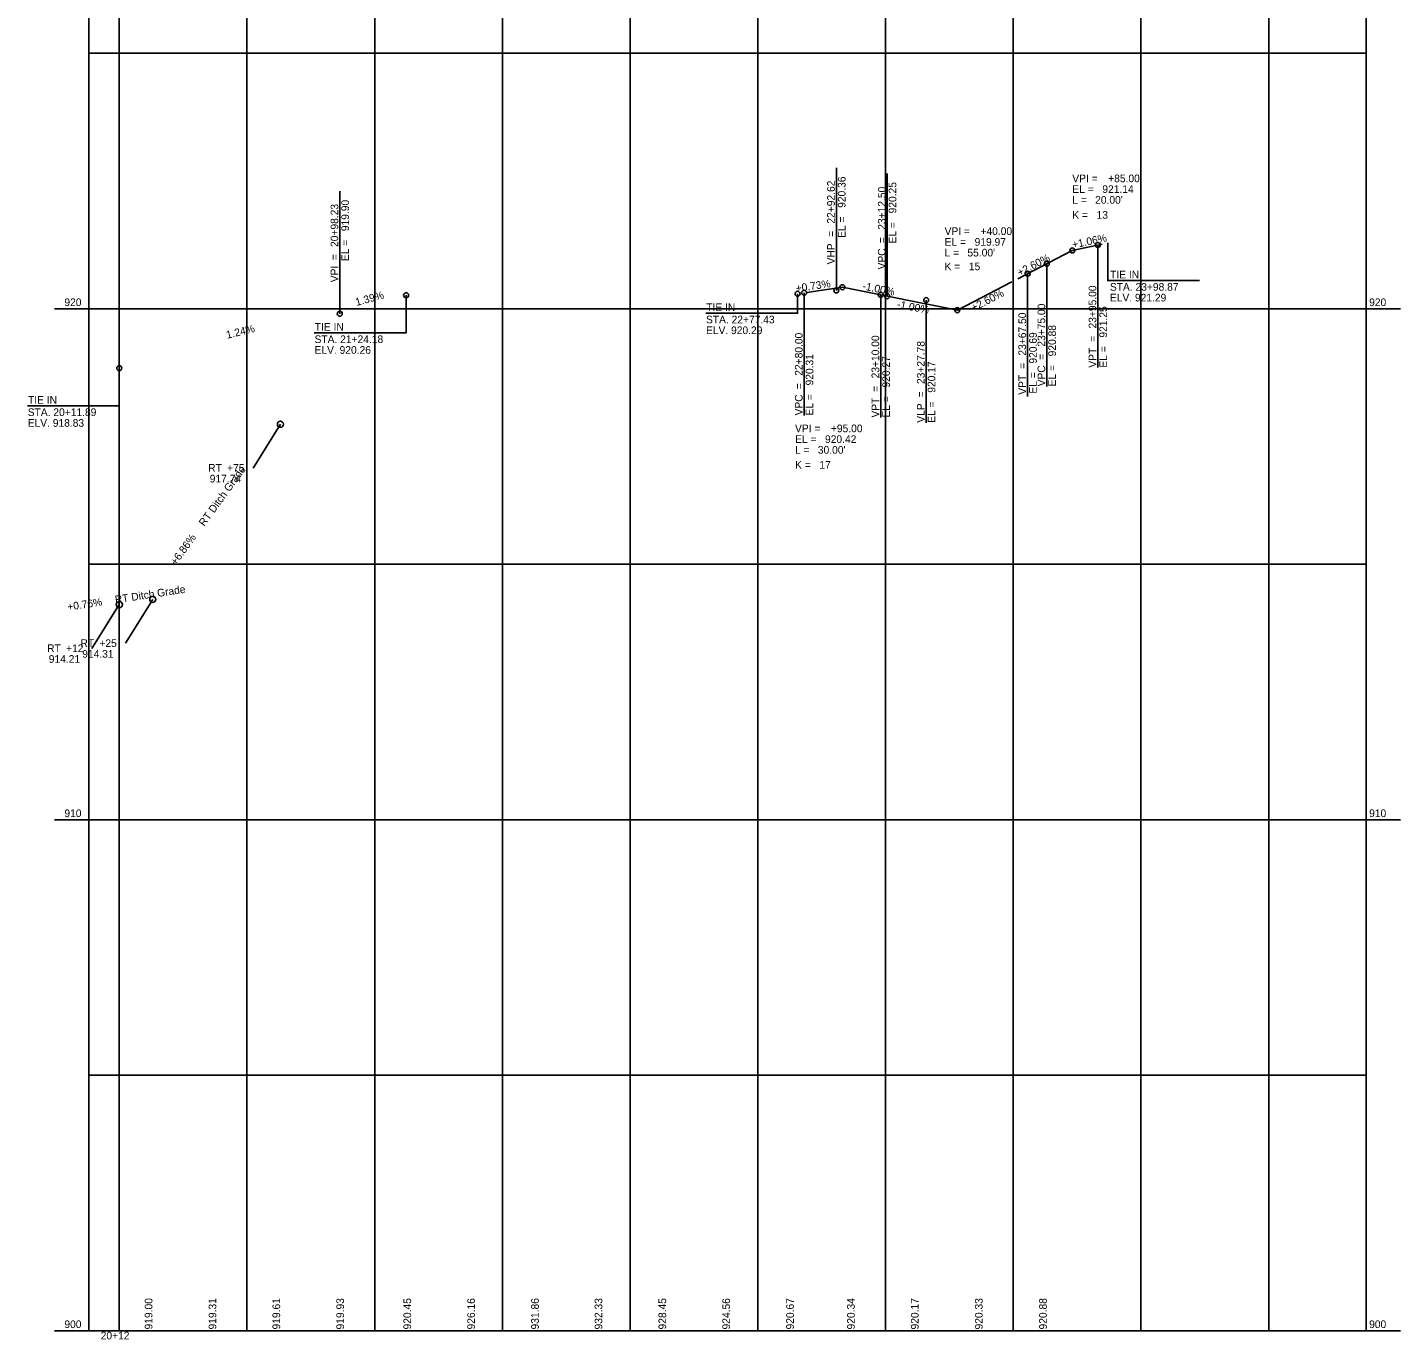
# Model space of a CAD drawing. Extents: x -36 to 502, y 897 to 1904.
# Drawn here: x -36 to 502, y 897 to 1410 of the extents above; entities that cross this region are included whole.
import ezdxf

# ---------------------------------------------------------------- set-up
doc = ezdxf.new("R2010")
doc.units = 0
for name, color, linetype in [('Text', 7, 'Continuous'), ('TextAlignment', 7, 'Continuous'), ('TextNonPlot', 7, 'Continuous')]:
    doc.layers.add(name, color=color, linetype=linetype)

msp = doc.modelspace()

# ---------------------------------------------------------------- linework, layer by layer
at = {"layer": 'Text'}
for centre in [(373.11, 1322.8), (383.11, 1324.93), (363.11, 1317.6), (355.61, 1313.7), (265.54, 1305.85), (268.11, 1306.22), (283.11, 1308.4), (298.11, 1305.4), (112.29, 1305.26), (300.61, 1304.9), (86.34, 1298.03), (328.11, 1299.4), (0, 1276.7)]:
    msp.add_circle(centre, 0.972, dxfattribs=at)
at = {"layer": 'TextAlignment'}
for p, q in [((280.73, 1307.14), (280.73, 1355.14)), ((300.61, 1304.9), (300.61, 1352.9)), ((86.34, 1298.03), (86.34, 1346.03)), ((373.11, 1322.8), (351.82, 1311.73)), ((373.11, 1322.8), (384.85, 1325.3)), ((373.11, 1322.8), (373.11, 1322.8)), ((383.11, 1324.93), (383.11, 1324.93)), ((383.11, 1324.93), (383.11, 1276.93)), ((363.11, 1317.6), (363.11, 1317.6)), ((363.11, 1317.6), (363.11, 1269.6)), ((355.61, 1313.7), (355.61, 1313.7)), ((355.61, 1265.7), (355.61, 1313.7)), ((283.11, 1308.4), (269.13, 1306.37)), ((283.11, 1308.4), (283.11, 1308.4)), ((283.11, 1308.4), (306.64, 1303.69)), ((328.11, 1299.4), (349.4, 1310.47)), ((268.11, 1306.22), (268.11, 1306.22)), ((268.11, 1306.22), (268.11, 1258.22)), ((298.11, 1305.4), (298.11, 1305.4)), ((298.11, 1305.4), (298.11, 1257.4)), ((300.61, 1304.9), (300.61, 1304.9)), ((328.11, 1299.4), (304.58, 1304.11)), ((315.89, 1303.37), (315.89, 1255.37)), ((328.11, 1299.4), (328.11, 1299.4)), ((63.11, 1254.8), (52.38, 1237.64)), ((0, 1184.2), (-10.73, 1167.04)), ((13.11, 1186.2), (2.38, 1169.04))]:
    msp.add_line(p, q, dxfattribs=at)
for points in [[(386.98, 1325.75), (386.98, 1311), (422.92, 1311)], [(112.29, 1305.26), (112.29, 1290.51), (76.35, 1290.51)], [(265.54, 1305.85), (265.54, 1298.22), (229.59, 1298.22)], [(0, 1276.7), (0, 1261.95), (-35.94, 1261.95)]]:
    msp.add_lwpolyline(points, dxfattribs=at)
for centre, radius in [((280.73, 1307.14), 0.972), ((315.89, 1303.37), 0.972), ((63.11, 1254.8), 1.2), ((0, 1184.2), 1.2), ((13.11, 1186.2), 1.2)]:
    msp.add_circle(centre, radius, dxfattribs=at)
at = {"layer": 'TextNonPlot'}
for p, q in [((-11.89, 900), (-11.89, 1900)), ((0, 900), (0, 1900)), ((50, 900), (50, 1900)), ((100, 900), (100, 1900)), ((150, 900), (150, 1900)), ((200, 900), (200, 1900)), ((250, 900), (250, 1900)), ((300, 900), (300, 1900)), ((350, 900), (350, 1900)), ((400, 900), (400, 1900)), ((450, 900), (450, 1900)), ((488.11, 900), (488.11, 1900)), ((-11.89, 1400), (488.11, 1400)), ((-11.89, 1300), (-25.39, 1300)), ((-11.89, 1300), (488.11, 1300)), ((501.61, 1300), (488.11, 1300)), ((-11.89, 1200), (488.11, 1200)), ((-11.89, 1100), (-25.39, 1100)), ((-11.89, 1100), (488.11, 1100)), ((501.61, 1100), (488.11, 1100)), ((-11.89, 1000), (488.11, 1000)), ((-11.89, 900), (-25.39, 900)), ((-11.89, 900), (488.11, 900)), ((501.61, 900), (488.11, 900))]:
    msp.add_line(p, q, dxfattribs=at)

# ---------------------------------------------------------------- texts
at = {"layer": 'TextAlignment'}
for s, rotation, p in [('22+92.62', 90, (280.13, 1333.3)), ('920.36', 90, (284.33, 1339.48)), ('920.25', 90, (304.21, 1337.3)), ('23+12.50', 90, (300.01, 1330.9)), ('20+98.23', 90, (85.74, 1324.16)), ('919.90', 90, (89.94, 1330.34)), ('EL = ', 90, (284.33, 1327.73)), ('EL = ', 90, (304.21, 1325.55)), (' = ', 90, (280.13, 1326.98)), (' = ', 90, (300.01, 1324.58)), ('+1.06%', 12.0038, (373.4, 1323.54)), ('EL = ', 90, (89.94, 1318.62)), ('VHP', 90, (280.13, 1317.34)), ('VPC', 90, (300.01, 1315.36)), (' = ', 90, (85.74, 1317.88)), ('+2.60%', 27.4744, (352.51, 1312.6)), ('VPI', 90, (85.74, 1310.36)), ('1.39%', 15.56, (92.9, 1301.04)), ('+0.73%', 8.2608, (265.05, 1306.47)), ('-1.00%', 348.6901, (290.8, 1307.54)), ('+2.60%', 27.4744, (334.48, 1298.81)), ('23+95.00', 90, (382.51, 1292.25)), ('-1.00%', 348.6901, (304.28, 1300.43)), ('23+75.00', 90, (362.51, 1285.14)), ('23+67.50', 90, (355.01, 1281.64)), ('921.25', 90, (386.71, 1288.68)), ('1.24%', 13.8787, (42.24, 1288.22)), ('22+80.00', 90, (267.51, 1273.76)), ('920.69', 90, (359.21, 1278.5)), ('920.88', 90, (366.71, 1281.35)), ('23+10.00', 90, (297.51, 1272.72)), ('23+27.78', 90, (315.29, 1270.51)), (' = ', 90, (382.51, 1285.94)), ('EL = ', 90, (386.71, 1276.93)), ('920.31', 90, (271.71, 1269.97)), ('920.27', 90, (301.71, 1269.15)), (' = ', 90, (362.51, 1278.82)), ('VPT', 90, (382.51, 1276.93)), ('920.17', 90, (319.49, 1267.12)), ('VPT', 90, (355.01, 1266.32)), (' = ', 90, (355.01, 1275.33)), ('EL = ', 90, (359.21, 1266.75)), ('VPC', 90, (362.51, 1269.6)), ('EL = ', 90, (366.71, 1269.6)), (' = ', 90, (267.51, 1267.44)), (' = ', 90, (297.51, 1266.41)), ('VPC', 90, (267.51, 1258.22)), ('EL = ', 90, (271.71, 1258.22)), ('VPT', 90, (297.51, 1257.4)), ('EL = ', 90, (301.71, 1257.4)), (' = ', 90, (315.29, 1264.2)), ('EL = ', 90, (319.49, 1255.37)), ('VLP', 90, (315.29, 1255.37)), (' RT Ditch Grade', 53.9131, (32.63, 1213.69)), ('+6.86%', 53.9131, (22.19, 1199.36)), (' RT Ditch Grade', 8.6739, (-2.57, 1184.47)), ('+0.76%', 8.6739, (-20.09, 1181.79))]:
    msp.add_text(s, height=3, rotation=rotation, dxfattribs=at).set_placement(p)
for s, p in [('VPI = ', (373.11, 1349.5)), ('+85.00', (387.16, 1349.5)), ('EL = ', (373.11, 1345.3)), ('L = ', (373.11, 1341.1)), ("20.00'", (382.05, 1341.1)), ('921.14', (384.86, 1345.3)), ('K = ', (373.11, 1335.22)), ('13', (382.61, 1335.22)), ('VPI = ', (323.12, 1328.85)), ('+40.00', (337.16, 1328.85)), ('EL = ', (323.12, 1324.65)), ('L = ', (323.12, 1320.45)), ("55.00'", (332.05, 1320.45)), ('919.97', (334.87, 1324.65)), ('K = ', (323.12, 1315.05)), ('15', (332.62, 1315.05)), ('TIE IN', (387.91, 1311.84)), ('STA. 23+98.87', (387.82, 1307.04)), ('TIE IN', (229.79, 1299.06)), ('ELV. 921.29', (387.82, 1302.84)), ('STA. 22+77.43', (229.7, 1294.26)), ('TIE IN', (76.55, 1291.35)), ('ELV. 920.29', (229.7, 1290.06)), ('STA. 21+24.18', (76.45, 1286.55)), ('ELV. 920.26', (76.45, 1282.35)), ('TIE IN', (-35.74, 1262.79)), ('STA. 20+11.89', (-35.84, 1257.99)), ('ELV. 918.83', (-35.84, 1253.79)), ('VPI = ', (264.56, 1251.65)), ('+95.00', (278.6, 1251.65)), ('EL = ', (264.56, 1247.45)), ('920.42', (276.3, 1247.45)), ('L = ', (264.56, 1243.25)), ("30.00'", (273.49, 1243.25)), ('RT ', (34.81, 1236.2)), ('+75', (42.22, 1236.2)), ('K = ', (264.56, 1237.37)), ('17', (274.06, 1237.37)), ('917.74', (35.41, 1232)), ('RT ', (-28.23, 1165.6)), ('+12', (-20.82, 1165.6)), ('RT ', (-15.19, 1167.6)), ('+25', (-7.78, 1167.6)), ('914.21', (-27.6, 1161.4)), ('914.31', (-14.49, 1163.4))]:
    msp.add_text(s, height=3, dxfattribs=at).set_placement(p)
at = {"layer": 'TextNonPlot'}
for s, p in [('920', (-21.49, 1301.02)), ('920', (489.31, 1301.02)), ('910', (-21.49, 1101.02)), ('910', (489.31, 1101.02)), ('900', (-21.49, 901.02)), ('900', (489.31, 901.02)), ('20+12', (-7.27, 896.58))]:
    msp.add_text(s, height=3, dxfattribs=at).set_placement(p)
for s, p in [('919.00', (12.98, 900.48)), ('919.31', (37.98, 900.48)), ('919.61', (62.98, 900.48)), ('919.93', (87.99, 900.48)), ('920.45', (114.25, 900.48)), ('926.16', (139.25, 900.48)), ('931.86', (164.25, 900.48)), ('932.33', (189.1, 900.48)), ('928.45', (214.1, 900.48)), ('924.56', (239.1, 900.48)), ('920.67', (264.1, 900.48)), ('920.34', (287.94, 900.48)), ('920.17', (312.93, 900.48)), ('920.33', (338, 900.48)), ('920.88', (363.12, 900.48))]:
    msp.add_text(s, height=3, rotation=90, dxfattribs=at).set_placement(p)

doc.saveas('drawing.dxf')
